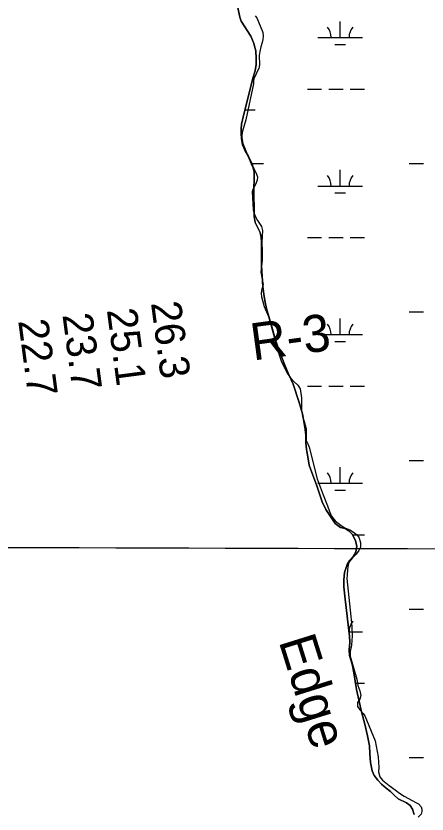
# Model space of a CAD drawing. Extents: x 3161564 to 3199464, y 849354 to 874788.
# Drawn here: x 3176670 to 3177591, y 860252 to 862040 of the extents above; entities that cross this region are included whole.
import ezdxf

# ---------------------------------------------------------------- set-up
doc = ezdxf.new("R2010")
doc.units = 0
for name, color, linetype in [('V-GRID-MAJR', 7, 'Continuous'), ('V-RIVR-IDEN', 7, 'Continuous'), ('V-RIVR-RANG', 7, 'Continuous'), ('V-RIVR-RANG-IDEN', 7, 'Continuous'), ('V-ROAD-CNTR', 7, 'Continuous'), ('V-SITE-VEGE', 7, 'Continuous'), ('V-TOPO-SHOR', 7, 'Continuous'), ('V-WETL-SWMP', 7, 'Continuous')]:
    doc.layers.add(name, color=color, linetype=linetype)

msp = doc.modelspace()

# ---------------------------------------------------------------- linework, layer by layer
at = {"layer": 'V-GRID-MAJR'}
msp.add_spline([(3165780.446, 860882.501), (3171010.106, 860866.147), (3176239.768, 860850.5530000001), (3181469.433, 860835.721), (3186699.099, 860821.649), (3191928.768, 860808.338), (3197158.438, 860795.787), (3197158.4390000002, 860795.787)], degree=3, dxfattribs=at)
at = {"layer": 'V-ROAD-CNTR'}
msp.add_spline([(3176879.125204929, 855651.914668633), (3176902.292158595, 855659.0856542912), (3176934.1140949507, 855666.9976384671), (3176983.4499962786, 855657.7056570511), (3177040.651881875, 855639.063694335), (3177110.477742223, 855613.5507453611), (3177170.583622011, 855601.7607689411), (3177236.7824896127, 855586.883798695), (3177274.782413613, 855573.5288254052), (3177317.445328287, 855579.7618129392), (3177362.5952379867, 855595.691781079), (3177411.9501392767, 855643.142686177), (3177451.732059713, 855679.194614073), (3177476.657009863, 855705.7895608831), (3177478.2700066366, 855736.9544985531), (3177464.172034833, 855782.2774079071), (3177430.750101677, 855833.3963056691), (3177372.994217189, 855887.769196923), (3177287.8353875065, 855954.8300628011), (3177219.8185235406, 855998.4419755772), (3177152.9756572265, 856039.3918936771), (3177089.341784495, 856079.2398139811), (3177023.387916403, 856134.3197038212), (3176966.6300299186, 856207.9345565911), (3176895.2451726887, 856290.0793923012), (3176782.2483986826, 856425.1231222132), (3176693.1625768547, 856545.301881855), (3176615.1687328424, 856622.647727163), (3176543.920875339, 856726.504519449), (3176474.3930143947, 856784.205404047), (3176414.352134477, 856823.5773253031), (3176395.899171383, 856827.976316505), (3176350.8212615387, 856806.1753601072), (3176279.148404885, 856754.702463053), (3176211.5535400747, 856707.4195576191), (3176172.2526186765, 856696.1065802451), (3176141.127680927, 856702.011568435), (3176111.749739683, 856719.5775333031), (3176032.565898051, 856777.3694177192), (3175933.5790960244, 856857.4342575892), (3175839.0062851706, 856930.2601119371), (3175807.1383489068, 856951.5090694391), (3175770.0914230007, 856958.6680551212), (3175787.1193889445, 856991.3959896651), (3175795.0863730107, 857040.6808910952), (3175799.484364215, 857113.7327449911), (3175810.823341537, 857206.9175586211), (3175813.712335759, 857287.3653977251), (3175807.7513476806, 857386.8311987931), (3175805.684351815, 857497.9369765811), (3175801.940359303, 857543.6058852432), (3175783.4633962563, 857620.527731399), (3175760.235442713, 857716.1135402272), (3175755.326452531, 857765.5174414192), (3175754.5264541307, 857815.6403411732), (3175751.6894598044, 857884.276203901), (3175756.309450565, 858015.455941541), (3175754.854453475, 858158.5586553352), (3175753.0504570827, 858270.798430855), (3175748.5974659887, 858321.6503291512), (3175736.501490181, 858372.0042284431), (3175677.161608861, 858555.5318613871), (3175602.2427586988, 858747.092478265), (3175558.2188467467, 858866.8562387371), (3175502.5159581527, 858986.2220000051), (3175436.2770906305, 859092.6197872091), (3175371.236220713, 859185.1206022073), (3175300.6823618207, 859261.5774492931), (3175219.099524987, 859367.2332379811), (3175166.218630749, 859443.6520851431), (3175175.325612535, 859507.1279581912), (3175222.0015191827, 859537.876896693), (3175285.3383925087, 859568.346835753), (3175321.1713208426, 859607.463757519), (3175310.2993425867, 859667.2116380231), (3175262.407438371, 859798.6233751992), (3175224.637513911, 859877.8702167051), (3175174.7256137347, 859982.0350083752), (3175144.840673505, 860115.364741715), (3175122.609717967, 860284.7894028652), (3175088.432786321, 860568.568835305), (3175086.2807906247, 860704.5445633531), (3175072.201818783, 860854.517263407), (3175052.526858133, 860999.933972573), (3175047.503868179, 861166.800638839), (3175053.177856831, 861343.7312849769), (3175066.700829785, 861550.381871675), (3175065.4638322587, 861662.491647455), (3175040.178882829, 861767.7534369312), (3175017.8369275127, 861884.1612041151), (3175008.363946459, 862033.901904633), (3174979.613003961, 862160.277651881), (3174952.1400589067, 862274.6484231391), (3174921.634119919, 862422.8161268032), (3174896.957169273, 862525.547921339), (3174861.7462396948, 862663.2186459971), (3174841.1032809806, 862738.0144964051)], degree=3, dxfattribs=at)
at = {"layer": 'V-SITE-VEGE'}
for p, q in [((3177205.863, 862039.5819999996), (3177209.257, 862035.6929999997)), ((3177209.257, 862035.6929999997), (3177222.254, 862004.7129999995)), ((3177222.254, 862004.7129999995), (3177222.802, 862002.4209999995)), ((3177222.802, 862002.4209999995), (3177223.441, 861994.2719999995)), ((3177221.594, 861980.0039999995), (3177218.647, 861970.3149999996)), ((3177222.946, 861987.1329999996), (3177221.594, 861980.0039999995)), ((3177223.441, 861994.2719999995), (3177222.946, 861987.1329999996)), ((3177218.647, 861970.3149999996), (3177215.98, 861960.3389999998)), ((3177215.98, 861960.3389999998), (3177215.038, 861951.2049999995)), ((3177215.038, 861951.2049999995), (3177215.698, 861930.0549999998)), ((3177215.698, 861930.0549999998), (3177213.762, 861921.6439999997)), ((3177209.116, 861913.6849999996), (3177206.1890000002, 861906.2839999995)), ((3177213.762, 861921.6439999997), (3177209.116, 861913.6849999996)), ((3177203.125, 861899.3119999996), (3177202.0810000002, 861894.4649999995)), ((3177202.0810000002, 861894.4649999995), (3177202.3000000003, 861887.4629999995)), ((3177206.1890000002, 861906.2839999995), (3177203.125, 861899.3119999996)), ((3177202.3000000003, 861887.4629999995), (3177184.8300000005, 861806.7629999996)), ((3177184.83, 861806.7629999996), (3177177.4560000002, 861781.8309999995)), ((3177176.0870000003, 861773.1289999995), (3177175.8910000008, 861767.2739999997)), ((3177175.8910000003, 861767.2739999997), (3177177.765, 861753.6829999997)), ((3177177.4560000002, 861781.8309999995), (3177176.0870000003, 861773.1289999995)), ((3177177.765, 861753.6829999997), (3177195.089, 861711.8039999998)), ((3177195.089, 861711.8039999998), (3177198.5930000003, 861704.6269999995)), ((3177198.5930000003, 861704.6269999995), (3177202.6750000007, 861698.3029999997)), ((3177202.6750000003, 861698.3029999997), (3177207.303, 861688.8289999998)), ((3177207.303, 861688.8289999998), (3177210.6450000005, 861679.5149999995)), ((3177210.6450000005, 861679.5149999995), (3177210.0020000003, 861671.9479999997)), ((3177206.486, 861662.4079999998), (3177200.518, 861650.7489999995)), ((3177210.002, 861671.9479999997), (3177206.486, 861662.4079999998)), ((3177200.518, 861650.7489999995), (3177199.0460000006, 861645.9049999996)), ((3177199.046, 861645.9049999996), (3177201.1, 861605.7419999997)), ((3177201.1, 861605.7419999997), (3177203.731, 861597.0009999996)), ((3177203.731, 861597.0009999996), (3177206.521, 861589.6899999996)), ((3177206.521, 861589.6899999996), (3177210.7290000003, 861581.2209999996)), ((3177210.7290000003, 861581.2209999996), (3177220.0290000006, 861567.8479999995)), ((3177220.029, 861567.8479999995), (3177222.237, 861559.2539999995)), ((3177222.237, 861559.2539999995), (3177220.9880000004, 861532.5499999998)), ((3177220.988, 861532.5499999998), (3177221.52, 861512.9739999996)), ((3177221.52, 861512.9739999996), (3177221.619, 861492.9709999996)), ((3177221.619, 861492.9709999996), (3177218.649, 861465.7119999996)), ((3177218.649, 861465.7119999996), (3177223.9620000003, 861437.9449999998)), ((3177223.9620000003, 861437.9449999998), (3177219.98, 861424.5529999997)), ((3177219.98, 861424.5529999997), (3177219.202, 861417.7009999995)), ((3177219.202, 861417.7009999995), (3177220.136, 861410.5509999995)), ((3177220.136, 861410.5509999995), (3177226.075, 861388.7809999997)), ((3177226.075, 861388.7809999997), (3177235.865, 861366.2589999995)), ((3177235.865, 861366.2589999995), (3177259.2100000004, 861280.4639999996)), ((3177259.21, 861280.4639999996), (3177264.088, 861267.4159999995)), ((3177264.088, 861267.4159999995), (3177269.966, 861254.3619999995)), ((3177269.966, 861254.3619999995), (3177277.4, 861239.5779999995)), ((3177277.4, 861239.5779999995), (3177284.8710000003, 861228.9339999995)), ((3177284.8710000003, 861228.9339999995), (3177292.656, 861220.8609999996)), ((3177292.656, 861220.8609999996), (3177301.294, 861212.6379999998)), ((3177301.294, 861212.6379999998), (3177306.361, 861204.7329999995)), ((3177306.361, 861204.7329999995), (3177309.318, 861184.7039999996)), ((3177309.318, 861184.7039999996), (3177309.2180000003, 861173.8469999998)), ((3177309.2180000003, 861173.8469999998), (3177309.353, 861157.8439999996)), ((3177309.353, 861157.8439999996), (3177310.682, 861147.1189999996)), ((3177310.682, 861147.1189999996), (3177312.609, 861139.3859999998)), ((3177312.609, 861139.3859999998), (3177315.679, 861131.6399999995)), ((3177315.679, 861131.6399999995), (3177319.6670000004, 861114.7459999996)), ((3177319.667, 861114.7459999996), (3177319.882, 861091.8839999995)), ((3177319.882, 861091.8839999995), (3177319.7100000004, 861088.7449999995)), ((3177319.7100000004, 861088.7449999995), (3177324.066, 861081.1299999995)), ((3177324.066, 861081.1299999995), (3177326.857, 861073.9619999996)), ((3177326.857, 861073.9619999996), (3177344.9080000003, 861002.7879999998)), ((3177344.9080000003, 861002.7879999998), (3177357.7180000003, 860967.0959999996)), ((3177357.718, 860967.0959999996), (3177367.489, 860942.5749999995)), ((3177367.489, 860942.5749999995), (3177372.2260000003, 860929.6719999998)), ((3177372.2260000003, 860929.6719999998), (3177376.8470000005, 860919.4859999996)), ((3177376.8470000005, 860919.4859999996), (3177384.7460000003, 860908.6969999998)), ((3177384.7460000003, 860908.6969999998), (3177398.2280000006, 860898.8559999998)), ((3177398.228, 860898.8559999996), (3177406.75, 860893.6339999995)), ((3177406.75, 860893.6339999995), (3177417.989, 860888.5279999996)), ((3177417.989, 860888.5279999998), (3177425.659, 860883.5989999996)), ((3177425.659, 860883.5989999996), (3177432.3230000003, 860878.6789999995)), ((3177432.323, 860878.6789999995), (3177438.272, 860872.7669999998)), ((3177438.272, 860872.7669999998), (3177441.732000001, 860860.7329999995)), ((3177441.732, 860860.7329999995), (3177441.775, 860850.0179999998)), ((3177437.988, 860842.3379999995), (3177431.629, 860834.5409999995)), ((3177441.775, 860850.0179999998), (3177437.988, 860842.3379999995)), ((3177423.693, 860826.0419999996), (3177416.461, 860816.8239999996)), ((3177431.629, 860834.5409999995), (3177423.693, 860826.0419999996)), ((3177413.688, 860810.4189999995), (3177412.16, 860799.8619999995)), ((3177416.461, 860816.8239999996), (3177413.688, 860810.4189999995)), ((3177411.9020000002, 860787.4369999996), (3177411.401, 860779.7239999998)), ((3177412.16, 860799.8619999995), (3177411.9020000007, 860787.4369999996)), ((3177411.401, 860779.7239999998), (3177420.039, 860694.9249999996)), ((3177420.039, 860694.9249999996), (3177421.972, 860672.4759999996)), ((3177421.972, 860672.4759999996), (3177422.7750000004, 860651.3249999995)), ((3177422.775, 860651.3249999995), (3177421.1550000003, 860630.9099999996)), ((3177421.1550000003, 860630.9099999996), (3177418.45, 860616.5069999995)), ((3177418.45, 860616.5069999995), (3177418.6380000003, 860606.0739999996)), ((3177418.6380000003, 860606.0739999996), (3177433.154, 860554.2229999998)), ((3177433.154, 860554.2229999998), (3177435.598, 860540.3419999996)), ((3177435.598, 860540.3419999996), (3177439.767, 860528.0169999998)), ((3177439.7670000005, 860528.0169999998), (3177442.2440000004, 860517.7049999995)), ((3177442.244, 860517.7049999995), (3177439.88, 860509.4409999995)), ((3177434.809, 860501.9189999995), (3177434.5840000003, 860493.0609999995)), ((3177439.88, 860509.4409999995), (3177434.809, 860501.9189999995)), ((3177434.5840000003, 860493.0609999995), (3177439.802, 860485.8709999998)), ((3177439.802, 860485.8709999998), (3177447.5850000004, 860477.6539999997)), ((3177447.585, 860477.6539999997), (3177451.394, 860472.4749999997)), ((3177451.394, 860472.4749999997), (3177474.4420000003, 860416.3989999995)), ((3177474.4420000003, 860416.3989999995), (3177481.389, 860380.1899999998)), ((3177481.389, 860380.1899999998), (3177482.7430000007, 860356.6029999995)), ((3177482.7430000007, 860356.6029999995), (3177481.9360000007, 860346.7539999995)), ((3177481.936, 860346.7539999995), (3177484.977, 860335.8669999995)), ((3177484.977, 860335.8669999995), (3177490.6190000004, 860328.2419999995)), ((3177490.6190000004, 860328.2419999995), (3177505.7990000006, 860316.6709999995)), ((3177505.7990000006, 860316.6709999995), (3177519.1380000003, 860306.8329999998)), ((3177519.1380000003, 860306.8329999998), (3177528.634, 860298.8859999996)), ((3177528.634, 860298.8859999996), (3177539.149, 860292.6439999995)), ((3177539.149, 860292.6439999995), (3177557.054, 860282.4779999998)), ((3177557.054, 860282.4779999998), (3177565.4450000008, 860277.9699999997)), ((3177565.4450000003, 860277.9699999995), (3177571.843, 860274.9099999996)), ((3177571.843, 860274.9099999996), (3177577.3540000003, 860268.5719999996)), ((3177577.3540000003, 860268.5719999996), (3177579.165, 860263.4129999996)), ((3177577.489, 860252.4279999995), (3177571.134, 860245.0569999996)), ((3177579.257, 860257.9819999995), (3177577.4890000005, 860252.4279999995)), ((3177579.165, 860263.4129999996), (3177579.257, 860257.9819999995))]:
    msp.add_line(p, q, dxfattribs=at)
at = {"layer": 'V-TOPO-SHOR'}
for points in [[(3177166.704000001, 862058.2499999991), (3177171.250000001, 862036.9319999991), (3177174.441000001, 862028.0659999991), (3177196.219000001, 861994.4789999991), (3177202.136000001, 861979.8579999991), (3177207.362000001, 861961.153999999), (3177208.352000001, 861944.2889999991), (3177207.899000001, 861931.037999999), (3177205.472000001, 861916.3309999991), (3177200.577000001, 861900.503999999), (3177177.288000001, 861807.2769999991), (3177175.397000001, 861797.6419999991), (3177174.638000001, 861786.356999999), (3177174.554000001, 861777.1919999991), (3177175.086000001, 861764.258999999), (3177177.583000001, 861751.143999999), (3177182.709000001, 861739.3139999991), (3177191.085000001, 861724.998999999), (3177198.783000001, 861708.233999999), (3177203.355000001, 861689.535999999), (3177203.684000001, 861672.184999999), (3177202.871000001, 861655.337999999), (3177203.246000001, 861590.2039999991), (3177206.066000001, 861576.9199999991), (3177216.658000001, 861554.5659999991), (3177219.007000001, 861543.2509999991), (3177219.7320000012, 861533.2629999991), (3177219.6240000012, 861521.4809999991), (3177220.056000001, 861480.074999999), (3177222.895000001, 861433.7359999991), (3177224.859000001, 861416.207999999), (3177227.185000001, 861402.4389999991), (3177231.437000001, 861384.5619999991)], [(3177231.437000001, 861384.5619999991), (3177244.589000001, 861338.2889999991), (3177250.758000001, 861315.486999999), (3177259.523000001, 861290.2019999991), (3177270.377000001, 861261.1349999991), (3177281.910000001, 861234.189999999), (3177290.892000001, 861214.7949999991), (3177304.094000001, 861173.922999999), (3177311.8740000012, 861148.484999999), (3177317.326000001, 861118.812999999), (3177319.284000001, 861100.6309999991), (3177319.296000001, 861084.4299999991), (3177320.621000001, 861068.7069999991), (3177323.410000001, 861051.988999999), (3177326.679000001, 861033.7949999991), (3177334.650000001, 861011.135999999), (3177343.122000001, 860989.782999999), (3177356.025000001, 860951.8609999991), (3177363.879000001, 860934.275999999), (3177385.184000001, 860902.6569999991), (3177396.559000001, 860893.8779999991), (3177407.010000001, 860891.4899999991), (3177415.474000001, 860886.6639999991), (3177423.261000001, 860879.2259999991), (3177430.652000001, 860864.5929999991), (3177433.474000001, 860851.4759999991), (3177430.910000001, 860839.5519999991), (3177424.088000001, 860827.6699999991), (3177417.805000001, 860820.6919999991), (3177411.495000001, 860810.930999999), (3177406.092000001, 860793.1449999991), (3177404.300000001, 860776.633999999), (3177404.648000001, 860761.246999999), (3177407.501000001, 860733.7279999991), (3177417.033000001, 860650.341999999), (3177417.393000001, 860636.4299999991), (3177415.935000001, 860620.403999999), (3177416.793000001, 860607.3049999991), (3177422.667000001, 860587.7749999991), (3177426.415000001, 860568.5939999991), (3177432.774000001, 860531.059999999), (3177437.629000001, 860507.775999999), (3177443.763000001, 860481.0439999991), (3177451.038000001, 860453.974999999), (3177457.665000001, 860427.5659999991), (3177461.712000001, 860405.2719999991), (3177462.201000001, 860387.756999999), (3177463.817000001, 860367.9409999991), (3177467.567000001, 860348.920999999), (3177472.216000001, 860338.4049999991), (3177480.302000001, 860328.182999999), (3177488.727000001, 860319.2679999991), (3177498.795000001, 860310.6639999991), (3177508.707000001, 860303.207999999), (3177517.137000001, 860294.6179999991), (3177525.896000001, 860286.354999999), (3177544.308000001, 860277.672999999), (3177552.598000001, 860271.704999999), (3177558.414000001, 860263.631999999), (3177561.734000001, 860251.1639999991)]]:
    msp.add_lwpolyline(points, dxfattribs=at)
at = {"layer": 'V-WETL-SWMP'}
for p, q in [((3177171.2538515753, 862036.9330310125), (3177166.70684956, 862058.2500304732)), ((3177174.443850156, 862028.0670306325), (3177171.2538515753, 862036.9330310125)), ((3177196.222827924, 861994.4790246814), (3177174.443850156, 862028.0670306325)), ((3177396.0428841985, 861991.3264370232), (3177396.042867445, 862027.3264347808)), ((3177202.140824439, 861979.8590237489), (3177196.222827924, 861994.4790246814)), ((3177207.3668240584, 861961.1550236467), (3177202.140824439, 861979.8590237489)), ((3177346.042927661, 861991.3264370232), (3177446.0428407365, 861991.3264370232)), ((3177384.0429018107, 861975.8954379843), (3177408.0428809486, 861975.8954379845)), ((3177208.354830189, 861944.2900252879), (3177207.3668240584, 861961.1550236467)), ((3177207.90383714, 861931.0380271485), (3177208.354830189, 861944.2900252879)), ((3177205.4758482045, 861916.3330301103), (3177207.90383714, 861931.0380271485)), ((3177200.5818640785, 861900.5050343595), (3177205.4758482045, 861916.3330301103)), ((3177177.2919479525, 861807.2790568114), (3177200.5818640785, 861900.5050343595)), ((3177322.6350017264, 861875.8944442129), (3177354.634973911, 861875.8944442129)), ((3177370.634960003, 861875.8944442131), (3177402.634932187, 861875.8944442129)), ((3177418.6349182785, 861875.8944442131), (3177450.6348904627, 861875.8944442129)), ((3177182.834350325, 861829.4644471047), (3177205.5711250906, 861829.4644471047)), ((3177175.401955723, 861797.6420588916), (3177177.2919479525, 861807.2790568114)), ((3177174.5569667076, 861777.1940618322), (3177174.6419622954, 861786.3570606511)), ((3177174.6419622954, 861786.3570606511), (3177175.401955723, 861797.6420588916)), ((3177175.0899718, 861764.261063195), (3177174.5569667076, 861777.1940618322)), ((3177177.585973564, 861751.1450636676), (3177175.0899718, 861764.261063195)), ((3177182.712970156, 861739.3150627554), (3177177.585973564, 861751.1450636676)), ((3177191.088962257, 861724.9990606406), (3177182.712970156, 861739.3150627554)), ((3177198.786956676, 861708.2350591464), (3177191.088962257, 861724.9990606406)), ((3177198.255023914, 861709.3934545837), (3177224.727164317, 861709.3934545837)), ((3177203.3589574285, 861689.5370593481), (3177198.786956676, 861708.2350591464)), ((3177396.043039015, 861658.6514577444), (3177396.0430222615, 861694.651455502)), ((3177550.6348810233, 861709.3934545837), (3177582.6348532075, 861709.3934545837)), ((3177203.687964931, 861672.1870613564), (3177203.3589574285, 861689.5370593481)), ((3177202.875974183, 861655.3390638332), (3177203.687964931, 861672.1870613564)), ((3177346.0430824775, 861658.6514577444), (3177446.042995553, 861658.6514577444)), ((3177203.249003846, 861590.2040717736), (3177202.875974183, 861655.3390638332)), ((3177384.0430566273, 861643.2204587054), (3177408.043035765, 861643.2204587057)), ((3177206.0710051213, 861576.9220721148), (3177203.2490038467, 861590.2040717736)), ((3177216.6629971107, 861554.5670699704), (3177206.0710051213, 861576.9220721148)), ((3177219.011998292, 861543.2530702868), (3177216.6629971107, 861554.5670699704)), ((3177219.7370016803, 861533.2640711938), (3177219.011998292, 861543.2530702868)), ((3177219.627007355, 861521.4820727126), (3177219.7370016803, 861533.2640711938)), ((3177322.6351565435, 861543.2194649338), (3177354.6351287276, 861543.2194649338)), ((3177370.6351148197, 861543.2194649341), (3177402.635087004, 861543.2194649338)), ((3177418.635073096, 861543.2194649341), (3177450.63504528, 861543.2194649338)), ((3177220.059025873, 861480.0760776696), (3177219.627007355, 861521.4820727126)), ((3177222.8990425, 861433.7370821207), (3177220.059025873, 861480.0760776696)), ((3177224.863047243, 861416.2080833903), (3177222.8990425, 861433.7370821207)), ((3177227.189049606, 861402.4400840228), (3177224.863047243, 861416.2080833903)), ((3177231.4410505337, 861384.5630842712), (3177227.189049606, 861402.4400840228)), ((3177244.5920492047, 861338.2910839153), (3177231.4410505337, 861384.5630842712)), ((3177550.6350358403, 861376.7184753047), (3177582.635008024, 861376.7184753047)), ((3177396.043193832, 861325.9764784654), (3177396.043177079, 861361.976476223)), ((3177250.7610490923, 861315.4870838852), (3177244.5920492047, 861338.2910839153)), ((3177346.043237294, 861325.9764784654), (3177446.0431503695, 861325.9764784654)), ((3177259.526045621, 861290.2030829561), (3177250.7610490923, 861315.4870838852)), ((3177384.043211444, 861310.5454794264), (3177408.0431905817, 861310.5454794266)), ((3177270.382040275, 861261.1360815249), (3177259.526045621, 861290.2030829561)), ((3177281.913032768, 861234.1900795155), (3177270.382040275, 861261.1360815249)), ((3177290.8970261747, 861214.7960777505), (3177281.913032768, 861234.1900795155)), ((3177304.0980222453, 861173.9240766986), (3177290.8970261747, 861214.7960777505)), ((3177322.63531136, 861210.544485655), (3177354.635283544, 861210.544485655)), ((3177370.6352696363, 861210.5444856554), (3177402.6352418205, 861210.544485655)), ((3177418.6352279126, 861210.5444856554), (3177450.6352000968, 861210.544485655)), ((3177311.8790205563, 861148.4860762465), (3177304.0980222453, 861173.9240766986)), ((3177317.3300248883, 861118.8150774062), (3177311.8790205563, 861148.4860762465)), ((3177319.287029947, 861100.6320787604), (3177317.3300248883, 861118.8150774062)), ((3177319.300037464, 861084.4310807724), (3177319.287029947, 861100.6320787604)), ((3177320.6260424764, 861068.708082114), (3177319.300037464, 861084.4310807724)), ((3177323.415045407, 861051.9900828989), (3177320.6260424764, 861068.708082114)), ((3177326.682048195, 861033.7950836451), (3177323.415045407, 861051.9900828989)), ((3177334.6530448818, 861011.1370827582), (3177326.682048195, 861033.7950836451)), ((3177550.635190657, 861044.0434960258), (3177582.635162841, 861044.0434960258)), ((3177396.0433486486, 860993.3014991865), (3177396.0433318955, 861029.3014969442)), ((3177343.127040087, 860989.7840814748), (3177334.6530448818, 861011.1370827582)), ((3177356.028035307, 860951.8610801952), (3177343.1270400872, 860989.7840814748)), ((3177346.043392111, 860993.3014991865), (3177446.0433051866, 860993.3014991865)), ((3177384.043366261, 860977.8705001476), (3177408.0433453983, 860977.8705001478)), ((3177363.8830298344, 860934.2770787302), (3177356.028035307, 860951.8610801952)), ((3177385.1890075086, 860902.6580727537), (3177363.8830298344, 860934.2770787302)), ((3177396.5629918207, 860893.8780685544), (3177385.1890075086, 860902.6580727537)), ((3177407.0139747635, 860891.4900639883), (3177396.5629918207, 860893.8780685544)), ((3177415.477962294, 860886.6650606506), (3177407.0139747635, 860891.4900639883)), ((3177423.263952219, 860879.2280579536), (3177415.477962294, 860886.6650606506)), ((3177430.6549461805, 860864.5940563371), (3177423.263952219, 860879.2280579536)), ((3177423.9500971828, 860877.8695063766), (3177450.6353549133, 860877.8695063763)), ((3177433.4789473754, 860851.4760566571), (3177430.6549461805, 860864.5940563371)), ((3177424.0919747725, 860827.6710639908), (3177430.9129573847, 860839.5540593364)), ((3177430.9129573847, 860839.5540593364), (3177433.4789473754, 860851.4760566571)), ((3177411.499004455, 860810.9330719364), (3177417.807988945, 860820.6930677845)), ((3177417.807988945, 860820.6930677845), (3177424.0919747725, 860827.6710639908)), ((3177406.0960221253, 860793.1460766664), (3177411.499004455, 860810.9330719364)), ((3177404.3050329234, 860776.6340795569), (3177406.0960221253, 860793.1460766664)), ((3177404.6520394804, 860761.2480813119), (3177404.3050329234, 860776.6340795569)), ((3177407.505047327, 860733.7290834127), (3177404.6520394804, 860761.2480813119)), ((3177417.0360695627, 860650.3430893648), (3177407.505047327, 860733.7290834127)), ((3177550.6353454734, 860711.368516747), (3177582.6353176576, 860711.368516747)), ((3177415.860673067, 860660.6265199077), (3177446.043460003, 860660.6265199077)), ((3177417.3970754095, 860636.43009093), (3177417.0360695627, 860650.3430893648)), ((3177415.938085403, 860620.4060936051), (3177417.3970754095, 860636.43009093)), ((3177416.7980900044, 860607.3060948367), (3177415.938085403, 860620.4060936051)), ((3177422.6710888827, 860587.7770945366), (3177416.7980900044, 860607.3060948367)), ((3177426.4190912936, 860568.595095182), (3177422.6710888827, 860587.7770945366)), ((3177432.7780977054, 860531.061096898), (3177426.4190912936, 860568.595095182)), ((3177430.383613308, 860545.1945270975), (3177450.63550973, 860545.1945270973)), ((3177437.634100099, 860507.7770975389), (3177432.7780977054, 860531.061096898)), ((3177443.7671018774, 860481.0450980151), (3177437.634100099, 860507.7770975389)), ((3177451.0421018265, 860453.9760980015), (3177443.7671018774, 860481.0450980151)), ((3177457.669102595, 860427.5670982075), (3177451.0421018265, 860453.9760980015)), ((3177461.7151059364, 860405.2730991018), (3177457.669102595, 860427.5670982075)), ((3177462.2061132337, 860387.7581010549), (3177461.7151059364, 860405.2730991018)), ((3177463.8211196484, 860367.941102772), (3177462.206113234, 860387.7581010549)), ((3177550.63550029, 860378.693537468), (3177582.635472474, 860378.693537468)), ((3177467.57112198, 860348.9231033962), (3177463.8211196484, 860367.941102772)), ((3177472.2191187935, 860338.4061025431), (3177467.57112198, 860348.9231033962)), ((3177480.306109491, 860328.1851000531), (3177472.2191187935, 860338.4061025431)), ((3177488.7320989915, 860319.2690972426), (3177480.306109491, 860328.1851000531)), ((3177498.798085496, 860310.6650936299), (3177488.7320989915, 860319.2690972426)), ((3177508.711071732, 860303.2090899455), (3177498.798085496, 860310.6650936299)), ((3177517.141061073, 860294.6200870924), (3177508.711071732, 860303.2090899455)), ((3177525.900049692, 860286.3560840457), (3177517.141061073, 860294.6200870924)), ((3177544.312021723, 860277.6750765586), (3177525.900049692, 860286.3560840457)), ((3177552.6020100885, 860271.7060734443), (3177544.312021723, 860277.6750765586)), ((3177558.4180037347, 860263.6330717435), (3177552.602010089, 860271.7060734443)), ((3177561.7380037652, 860251.1650717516), (3177558.4180037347, 860263.6330717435))]:
    msp.add_line(p, q, dxfattribs=at)
for centre, radius, start, end in [((3177340.799995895, 861991.8012401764), 35.24628790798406, 359.2281793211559, 40.771837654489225), ((3177451.2857720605, 861991.8012401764), 35.24628790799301, 139.2281775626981, 180.77183589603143), ((3177340.8001507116, 861659.1262608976), 35.24628790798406, 359.2281793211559, 40.771837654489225), ((3177451.285926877, 861659.1262608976), 35.24628790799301, 139.2281775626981, 180.77183589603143), ((3177340.800305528, 861326.4512816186), 35.24628790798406, 359.2281793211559, 40.771837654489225), ((3177451.2860816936, 861326.4512816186), 35.24628790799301, 139.2281775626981, 180.77183589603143), ((3177340.8004603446, 860993.7763023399), 35.24628790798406, 359.2281793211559, 40.771837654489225), ((3177451.28623651, 860993.7763023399), 35.24628790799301, 139.2281775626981, 180.77183589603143), ((3177451.286391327, 860661.101323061), 35.24628790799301, 139.2281775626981, 180.77183589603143)]:
    msp.add_arc(centre, radius, start, end, dxfattribs=at)

# ---------------------------------------------------------------- texts
at = {"layer": 'V-RIVR-IDEN'}
msp.add_text('Edge', height=82.999832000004, rotation=287.3382252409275, dxfattribs=at).set_placement((3177257.940997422, 860639.6562915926))
at = {"layer": 'V-RIVR-RANG'}
for s, p in [('26.3', (3176972.2670221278, 861397.0285648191)), ('23.7', (3176774.055022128, 861370.3445648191)), ('25.1', (3176873.4720569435, 861381.3330125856)), ('22.7', (3176674.949022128, 861357.0025648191))]:
    msp.add_text(s, height=67.00000000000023, rotation=277.52832571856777, dxfattribs=at).set_placement(p)
at = {"layer": 'V-RIVR-RANG-IDEN'}
msp.add_text('R-3', height=82.999998, rotation=7.667402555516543, dxfattribs=at).set_placement((3177201.1148694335, 861267.883182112))

doc.saveas('drawing.dxf')
